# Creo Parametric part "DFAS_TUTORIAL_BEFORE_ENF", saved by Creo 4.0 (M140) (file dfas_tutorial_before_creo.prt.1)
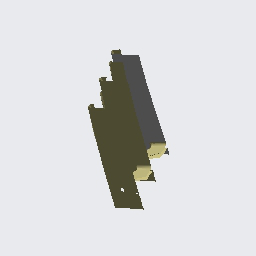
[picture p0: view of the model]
Units: ely_unitsystem; MM, GRAM, SECS

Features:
  1. coordinate system "CS0"
  2. imported feature
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
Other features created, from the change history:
  coordinate system "CS1"

Other named items: AXIS86_1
